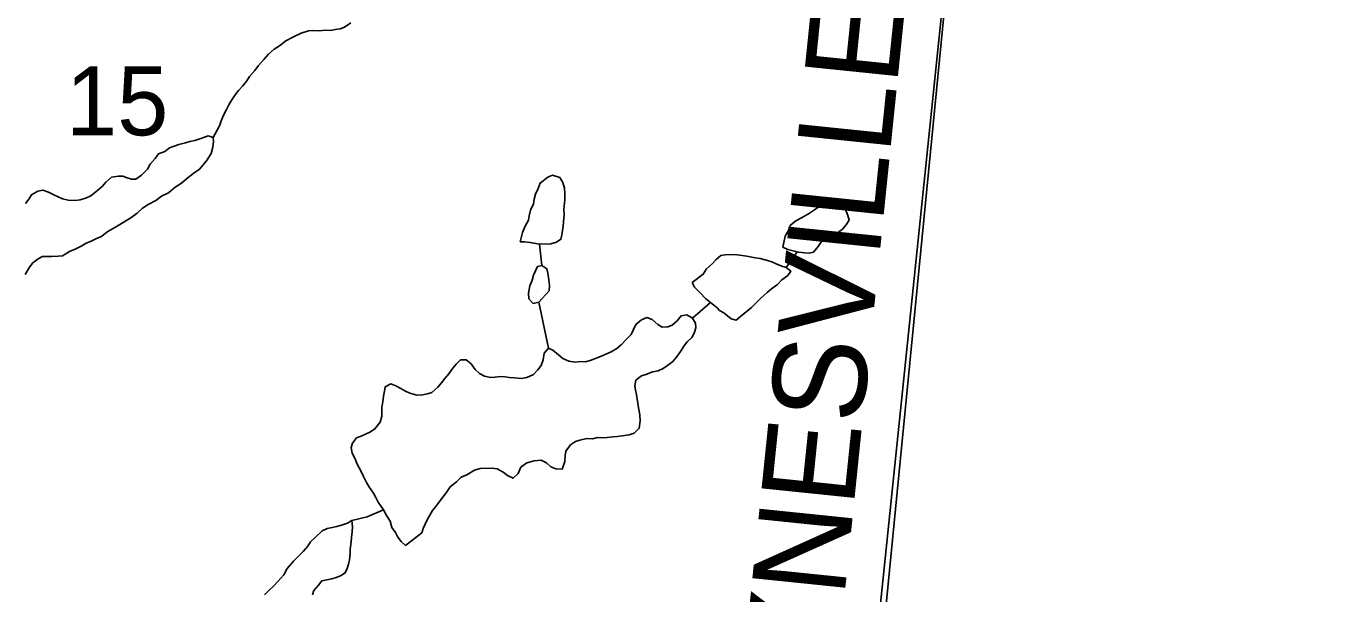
# Model space of a CAD drawing. Extents: x 0 to 1064, y 0 to 440.
# Drawn here: x 294.9 to 307.7, y 187.37 to 192.89 of the extents above; entities that cross this region are included whole.
import ezdxf

# ---------------------------------------------------------------- set-up
doc = ezdxf.new("R2010")
doc.units = 0
for name, color, linetype in [('GM_X_Minor_Lake', 7, 'Continuous'), ('GM_X_Minor_River', 7, 'Continuous'), ('GM_X_Section', 7, 'Continuous'), ('GM_X_Section_Text', 7, 'Continuous'), ('GM_X_Township_Road', 7, 'Continuous'), ('GM_X_Township_Road_Text', 7, 'Continuous')]:
    doc.layers.add(name, color=color, linetype=linetype)

msp = doc.modelspace()

# ---------------------------------------------------------------- linework, layer by layer
at = {"layer": 'GM_X_Minor_Lake'}
for points in [[(294.891, 190.472), (294.936, 190.544), (294.968, 190.585), (295.018, 190.626), (295.061, 190.649), (295.147, 190.647), (295.214, 190.651), (295.256, 190.655), (295.325, 190.696), (295.38, 190.718), (295.436, 190.747), (295.486, 190.776), (295.529, 190.793), (295.585, 190.821), (295.628, 190.838), (295.696, 190.891), (295.765, 190.931), (295.814, 190.96), (295.92, 191.024), (295.983, 191.07), (296.033, 191.117), (296.089, 191.152), (296.163, 191.192), (296.219, 191.233), (296.287, 191.267), (296.35, 191.32), (296.412, 191.36), (296.462, 191.401), (296.537, 191.46), (296.587, 191.495), (296.657, 191.578), (296.702, 191.649), (296.716, 191.709), (296.724, 191.764), (296.719, 191.806), (296.671, 191.82), (296.609, 191.798), (296.542, 191.775), (296.493, 191.765), (296.45, 191.754), (296.388, 191.738), (296.296, 191.704), (296.252, 191.669), (296.19, 191.647), (296.158, 191.599), (296.108, 191.546), (296.082, 191.498), (296.025, 191.439), (295.969, 191.398), (295.926, 191.4), (295.884, 191.413), (295.842, 191.427), (295.799, 191.428), (295.732, 191.418), (295.676, 191.371), (295.644, 191.33), (295.6, 191.294), (295.531, 191.236), (295.488, 191.219), (295.427, 191.197), (295.378, 191.192), (295.311, 191.194), (295.256, 191.208), (295.172, 191.247), (295.118, 191.273), (295.064, 191.293), (295.015, 191.282), (294.953, 191.248), (294.928, 191.206), (294.896, 191.164)], [(299.892, 190.769), (300.003, 190.77), (300.059, 190.786), (300.102, 190.815), (300.11, 190.858), (300.117, 190.9), (300.125, 190.942), (300.126, 190.985), (300.134, 191.051), (300.13, 191.106), (300.139, 191.203), (300.141, 191.257), (300.137, 191.312), (300.121, 191.367), (300.092, 191.417), (300.019, 191.437), (299.976, 191.42), (299.901, 191.362), (299.881, 191.308), (299.855, 191.254), (299.841, 191.206), (299.834, 191.158), (299.807, 191.098), (299.793, 191.044), (299.786, 191.001), (299.753, 190.942), (299.727, 190.882), (299.706, 190.791)], [(302.4, 190.693), (302.412, 190.689), (302.473, 190.682), (302.515, 190.68), (302.558, 190.691), (302.602, 190.744), (302.634, 190.792), (302.685, 190.833), (302.728, 190.856), (302.79, 190.878), (302.839, 190.913), (302.877, 190.954), (302.903, 191.002), (302.892, 191.045), (302.876, 191.088), (302.835, 191.144), (302.8, 191.206), (302.746, 191.207), (302.702, 191.191), (302.634, 191.15), (302.578, 191.109), (302.509, 191.063), (302.441, 191.022), (302.385, 190.994), (302.335, 190.953), (302.315, 190.899), (302.283, 190.845), (302.261, 190.737)], [(299.706, 190.791), (299.748, 190.79), (299.803, 190.782), (299.857, 190.774), (299.892, 190.769)], [(302.261, 190.737), (302.309, 190.717), (302.4, 190.693)], [(301.956, 190.151), (301.968, 190.163), (302.006, 190.204), (302.05, 190.245), (302.107, 190.298), (302.15, 190.333), (302.207, 190.374), (302.251, 190.421), (302.307, 190.462), (302.339, 190.504), (302.291, 190.541), (302.249, 190.555), (302.195, 190.575), (302.153, 190.594), (302.111, 190.608), (302.038, 190.628), (301.99, 190.636), (301.911, 190.65), (301.863, 190.658), (301.814, 190.665), (301.754, 190.667), (301.699, 190.663), (301.656, 190.658), (301.612, 190.617), (301.574, 190.576), (301.518, 190.529), (301.485, 190.475), (301.379, 190.394)], [(299.887, 190.203), (299.832, 190.192), (299.791, 190.236), (299.787, 190.291), (299.801, 190.363), (299.821, 190.417), (299.835, 190.465), (299.855, 190.507), (299.874, 190.549), (299.917, 190.56), (299.965, 190.528), (299.976, 190.485), (299.98, 190.443), (299.99, 190.364), (299.988, 190.315), (299.887, 190.203)], [(299.855, 190.507), (299.835, 190.465), (299.821, 190.417), (299.801, 190.363), (299.787, 190.291), (299.791, 190.236), (299.832, 190.192), (299.887, 190.203)], [(299.887, 190.203), (299.988, 190.315), (299.99, 190.364), (299.98, 190.443), (299.976, 190.485), (299.965, 190.528), (299.917, 190.56), (299.874, 190.549), (299.855, 190.507)], [(301.379, 190.394), (301.402, 190.35), (301.455, 190.294), (301.508, 190.238), (301.555, 190.2), (301.62, 190.147)], [(300.855, 189.177), (300.838, 189.305), (300.827, 189.348), (300.822, 189.391), (300.83, 189.445), (300.886, 189.486), (300.936, 189.503), (300.991, 189.525), (301.046, 189.536), (301.096, 189.558), (301.139, 189.587), (301.19, 189.628), (301.234, 189.682), (301.272, 189.735), (301.298, 189.777), (301.33, 189.818), (301.374, 189.859), (301.399, 189.901), (301.413, 189.955), (301.409, 189.998), (301.38, 190.047), (301.326, 190.079), (301.271, 190.069), (301.233, 190.022), (301.183, 189.981), (301.14, 189.964), (301.085, 189.959), (301.043, 189.985), (300.99, 190.035), (300.936, 190.055), (300.886, 190.032), (300.83, 189.985), (300.804, 189.932), (300.784, 189.89), (300.74, 189.843), (300.689, 189.789), (300.646, 189.754), (300.59, 189.72), (300.509, 189.686), (300.454, 189.663), (300.386, 189.635), (300.337, 189.624), (300.294, 189.626), (300.239, 189.621), (300.179, 189.629), (300.119, 189.655), (300.077, 189.693), (300.024, 189.737), (299.982, 189.757), (299.938, 189.709)], [(301.62, 190.147), (301.644, 190.124), (301.686, 190.099), (301.757, 190.042), (301.806, 190.028), (301.849, 190.063), (301.956, 190.151)], [(299.938, 189.709), (299.93, 189.643), (299.91, 189.589), (299.878, 189.547), (299.834, 189.5), (299.772, 189.472), (299.717, 189.461), (299.65, 189.469), (299.601, 189.471), (299.559, 189.478), (299.51, 189.48), (299.461, 189.475), (299.419, 189.471), (299.358, 189.485), (299.31, 189.51), (299.269, 189.548), (299.228, 189.604), (299.181, 189.642), (299.126, 189.643), (299.082, 189.602), (299.05, 189.561), (299.012, 189.507), (298.974, 189.46), (298.942, 189.418), (298.904, 189.377), (298.847, 189.324), (298.804, 189.313), (298.755, 189.303), (298.7, 189.298), (298.634, 189.319), (298.592, 189.338), (298.544, 189.364), (298.496, 189.39), (298.448, 189.409), (298.393, 189.381), (298.385, 189.339), (298.377, 189.29), (298.37, 189.236), (298.362, 189.181), (298.36, 189.139), (298.359, 189.096), (298.345, 189.036), (298.294, 188.971), (298.25, 188.942), (298.201, 188.919), (298.158, 188.902), (298.114, 188.885), (298.076, 188.832), (298.063, 188.79), (298.073, 188.735), (298.102, 188.679), (298.118, 188.636), (298.158, 188.556), (298.181, 188.507), (298.21, 188.451), (298.239, 188.402), (298.279, 188.346), (298.302, 188.303), (298.325, 188.26), (298.377, 188.185), (298.406, 188.13), (298.441, 188.074), (298.457, 188.013), (298.492, 187.963), (298.515, 187.92), (298.55, 187.876), (298.591, 187.839)], [(298.591, 187.839), (298.748, 187.961), (298.761, 188.003), (298.781, 188.045), (298.8, 188.087), (298.852, 188.177), (298.884, 188.218), (298.922, 188.266), (298.954, 188.307), (298.986, 188.349), (299.024, 188.408), (299.087, 188.455), (299.131, 188.502), (299.186, 188.524), (299.261, 188.571), (299.316, 188.587), (299.432, 188.59), (299.481, 188.582), (299.54, 188.55), (299.582, 188.518), (299.636, 188.492), (299.686, 188.539), (299.712, 188.599), (299.769, 188.64), (299.842, 188.662), (299.909, 188.666), (299.963, 188.64), (300.005, 188.602), (300.053, 188.583), (300.114, 188.581), (300.14, 188.653), (300.142, 188.714), (300.15, 188.756), (300.195, 188.815), (300.244, 188.85), (300.287, 188.861), (300.355, 188.877), (300.41, 188.875), (300.459, 188.886), (300.501, 188.885), (300.55, 188.889), (300.605, 188.894), (300.648, 188.898), (300.697, 188.903), (300.764, 188.913), (300.813, 188.93), (300.864, 188.977), (300.872, 189.049), (300.868, 189.104), (300.863, 189.147), (300.855, 189.177)], [(297.686, 187.357), (297.7, 187.399), (297.744, 187.452), (297.776, 187.493), (297.825, 187.504), (297.874, 187.515), (297.917, 187.525), (297.96, 187.542), (298.004, 187.571), (298.024, 187.613), (298.037, 187.655), (298.045, 187.698), (298.053, 187.758), (298.054, 187.801), (298.063, 187.873), (298.064, 187.916), (298.072, 187.97), (298.074, 188.019), (298.07, 188.079), (298.026, 188.056), (297.977, 188.04), (297.922, 188.023), (297.879, 188.012), (297.83, 188.002), (297.78, 187.979), (297.711, 187.914), (297.667, 187.873), (297.641, 187.831), (297.597, 187.778), (297.553, 187.737), (297.502, 187.684), (297.439, 187.613), (297.407, 187.553), (297.35, 187.488), (297.306, 187.441), (297.262, 187.4), (297.218, 187.359)]]:
    msp.add_lwpolyline(points, dxfattribs=at)
at = {"layer": 'GM_X_Minor_River'}
for points in [[(296.719, 191.806), (296.784, 191.926), (296.798, 191.968), (296.824, 192.028), (296.85, 192.076), (296.876, 192.129), (296.902, 192.171), (296.934, 192.219), (296.966, 192.26), (297.01, 192.307), (297.048, 192.355), (297.074, 192.396), (297.124, 192.456), (297.162, 192.503), (297.213, 192.562), (297.257, 192.615), (297.314, 192.662), (297.364, 192.697), (297.426, 192.744), (297.5, 192.784), (297.575, 192.818), (297.648, 192.84), (297.691, 192.845), (297.758, 192.843), (297.807, 192.847), (297.862, 192.846), (297.911, 192.856), (297.954, 192.861), (297.997, 192.878), (298.059, 192.919)], [(299.917, 190.56), (299.892, 190.769)], [(302.291, 190.541), (302.4, 190.693)], [(299.982, 189.757), (299.887, 190.203)], [(301.38, 190.047), (301.555, 190.2)], [(298.07, 188.079), (298.217, 188.117), (298.377, 188.185)]]:
    msp.add_lwpolyline(points, dxfattribs=at)
at = {"layer": 'GM_X_Section'}
for points in [[(288.758, 200.836), (304.455, 199.415), (302.913, 183.69), (287.113, 185.421)], [(321.14, 197.859), (319.799, 181.959), (302.913, 183.69), (304.455, 199.415)]]:
    msp.add_lwpolyline(points, close=True, dxfattribs=at)
at = {"layer": 'GM_X_Township_Road'}
msp.add_lwpolyline([(301.781, 175.609), (301.781, 175.638), (301.79, 176.169), (301.842, 176.698), (301.928, 177.092), (302.047, 177.619), (302.135, 178.092), (302.165, 178.42), (302.238, 178.802), (302.339, 179.001), (302.431, 179.382), (302.827, 183.579), (304.458, 199.328), (304.487, 199.714)], dxfattribs=at)

# ---------------------------------------------------------------- texts
at = {"layer": 'GM_X_Section_Text'}
msp.add_text('15', height=0.6697, rotation=0, dxfattribs=at).set_placement((295.289, 191.826))
at = {"layer": 'GM_X_Township_Road_Text'}
msp.add_text('WAYNESVILLE', height=0.90909, rotation=84.1267, dxfattribs=at).set_placement((302.574, 184.573))

doc.saveas('drawing.dxf')
